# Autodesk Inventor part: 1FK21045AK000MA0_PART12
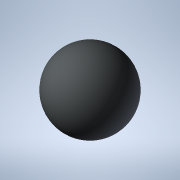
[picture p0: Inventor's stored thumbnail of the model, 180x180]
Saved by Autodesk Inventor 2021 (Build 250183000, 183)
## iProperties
Created: 2025-04
Part Number: 1FK21045AK000MA0_PART12
Material: Generic
Catalog Web Link: www.3dfindit.com
Description: -Servo synchronous motor
Document SubType Name: Modeling
Designer: psAdmin
Mass: 0.137258 g
Surface Area: 1.2868 cm^2
Volume: 0.137258 cm^3
Density: 1 g/cm^3
Appearance: PSOLRGB-212-217-219
Category: PARTsolutions
Title: 1FK21045AK000MA0_PART12
Author: Cadenas PARTsolutions
Comments: Servo synchronous motor
Sending System: PARTsolutions
Preprocessor: ST-DEVELOPER v19.3
PSOL_IDENT_0: {$CADENAS_DATA/23d-libs/siemens_ag/_cat_/3d/2f/1fk21045ak000ma0.prj},216 {VTYP=3D},{NB=1FK21045AK000
PSOL_IDENT_1: MA0_PART12},{LINA=1FK21045AK000MA0_PART12},{NN=1FK21045AK000MA0_PART12},{NOPRJ=TRUE},{DATE=19.08.202
PSOL_IDENT_2: 5 14:00:34},{GEOMDATE=30.07.2025 02:01:24},{VERSION=},{LINEID=10},{WBVAR=},{WBNUMERIC=}  {NB=1FK2104
PSOL_IDENT_3: 5AK000MA0_PART12},{LINA=1FK21045AK000MA0_PART12},{KT=DUMMY},{PREVIEW=../../../_pool_/a9/69/p_d211_xx
PSOL_IDENT_4: _00818j.png},{DESCSHORT=SIMOTICS S-1FK2 HD, SINAMICS S210 3AC 400V-480V, 1.7 Nm, 6000 rpm},{DESCLONG=
PSOL_IDENT_5: SIMOTICS S-1FK2 HD servo motor M0=2.4 Nm; PN = 1.07 kW at nN=6000 rpm (380-480 V); PN = 0.75 kW at n
PSOL_IDENT_6: N=3000 rpm (200-240 V); degree of protection IP64; cylindrical shaft D19x40mm; absolute encoder 22-b
PSOL_IDENT_7: it + 12-bit multiturn (encoder AM22DQC); with OCC interface; plug size M17, rotatable; SIMOTICS S-1F
PSOL_IDENT_8: K2 servomotorfor a wide range of uses in industrial environments. SIMOTICS S‑1FK2 servomotors are co
PSOL_IDENT_9: mpact synchronous motors with a high dynamic performance that set themselves apart as a result of th
PSOL_IDENT_10: eir high power density, degree of protection and overload capability. The motors are available in tw
PSOL_IDENT_11: o variants: as High Dynamic variant (highest dynamic performance as a result of the low intrinsic mo
PSOL_IDENT_12: ment of inertia for applications demanding a high dynamic performance with low moved masses) - and a
PSOL_IDENT_13: s Compact variant (precise and stable closed-loop control for medium up to large moved masses as a r
PSOL_IDENT_14: esult of a medium intrinsic moment of inertia). SIMOTICSS‑1FK2 servomotors fully exploit their stren
PSOL_IDENT_15: gths in a system with the SINAMICSS210 frequency converter and simple connection using the one cable
PSOL_IDENT_16: connection (OCC). Advantages include the short control and positioning times, fast and precise corr
PSOL_IDENT_17: ection of disturbing quantities as well as stable control with a high dynamic performance. The servo
PSOL_IDENT_18: motors can be configured to address a wide range of requirements. For example with and without hold
PSOL_IDENT_19: ing brake, IP64 or IP65 degree of protection, singleturn or multiturn absolute encoders - to name ju
PSOL_IDENT_20: st a few. Further, the servomotors are available in different shaft heights extending from 20 to 100
PSOL_IDENT_21: . A shaft sealing ring is available to achieve an IP65 degree of protection and for subsequent mount
PSOL_IDENT_22: ing at the motor or as spare part. SIMOTICS - the optimum motor for each and every motion control ap
PSOL_IDENT_23: plication.},{INTNO=804766789342},{SUPPLIERALTNO=1FK2104-5AK00-0MA0},{MANUID=1FK21045AK000MA0},{MANUN
PSOL_IDENT_24: AME=Siemens},{MANUTYPEDESC=Synchronous motor 1FK2-HD 2,39 Nm},{AAU732=SIMOTICS},{AAO057=S-1FK2},{AAU
PSOL_IDENT_25: 734=SIMOTICS S-1FK2 HD servo motor M0=2.4 Nm; PN = 1.07 kW at nN=6000 rpm (380-480 V); PN = 0.75 kW
PSOL_IDENT_26: at nN=3000 rpm (200-240 V); degree of protection IP64; cylindrical shaft D19x40mm; absolute encoder
PSOL_IDENT_27: 22-bit + 12-bit multiturn (encoder AM22DQC); with OCC interface; plug size M17, rotatable;},{AAW338=
PSOL_IDENT_28: Synchronous motor 1FK2-HD 2,39 Nm},{AAO742=SIMOTICS},{AAO663=4042948691151},{NOCUPEROU=1},{PRICEQUAN
PSOL_IDENT_29: TITY=1},{QUANTITYMIN=1},{QUANTITYINT=1},{CTN=85015100},{COO=DE},{AAO676=1FK2104-5AK00-0MA0},{AAO677=
PSOL_IDENT_30: Siemens AG},{ORDERUNIT=C62},{CONTENTUNIT=C62}
NB: 1FK21045AK000MA0_PART12
NT: Servo synchronous motor
NBSYN: $MANUID._PART12
LINA: 1FK21045AK000MA0_PART12
CATALOG: SIEMENS
PREVIEW: ../../../_pool_/a9/69/p_d211_xx_00818j.png
DESCSHORT: SIMOTICS S-1FK2 HD, SINAMICS S210 3AC 400V-480V, 1.7 Nm, 6000 rpm
DESCLONG: SIMOTICS S-1FK2 HD servo motor M0=2.4 Nm; PN = 1.07 kW at nN=6000 rpm (380-480 V); PN = 0.75 kW at nN=3000 rpm (200-240 V); degree of protection IP64; cylindric
INTNO: 804766789342
SUPPLIERALTNO: 1FK2104-5AK00-0MA0
MANUID: 1FK21045AK000MA0
MANUNAME: Siemens
MANUTYPEDESC: Synchronous motor 1FK2-HD 2,39 Nm
AAU732: SIMOTICS
AAO057: S-1FK2
AAU734: SIMOTICS S-1FK2 HD servo motor M0=2.4 Nm; PN = 1.07 kW at nN=6000 rpm (380-480 V); PN = 0.75 kW at nN=3000 rpm (200-240 V); degree of protection IP64; cylindric
AAW338: Synchronous motor 1FK2-HD 2,39 Nm
AAO742: SIMOTICS
AAO663: 4042948691151.0
NOCUPEROU: 1
PRICEQUANTITY: 1
QUANTITYMIN: 1
QUANTITYINT: 1
CTN: 85015100
COO: DE
ARTICLENO: 1FK21045AK000MA0_PART12
BOMINFO: 1FK21045AK000MA0_PART12
CREATOR: CADENAS GmbH
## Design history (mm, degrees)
feature "2025_04_17_15_39_51_0728"
body "Solid1"
